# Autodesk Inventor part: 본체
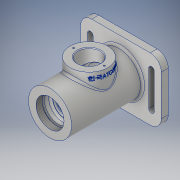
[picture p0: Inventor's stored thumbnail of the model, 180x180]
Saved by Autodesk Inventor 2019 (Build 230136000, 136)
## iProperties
Created: 2021-07
Part Number: 본체
Material: 알루미늄 6061
Document SubType Name: Modeling
Designer: jun-2-7
Mass: 744.735 g
Surface Area: 645.369 cm^2
Volume: 275.828 cm^3
Density: 2.7 g/cm^3
Appearance: 알루미늄 - 평지
Author: jun-2-7
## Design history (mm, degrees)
sketch "스케치1"
  geometry: L1 (0, 51)-(31, 51); L2 (31, 51)-(31, -51); L3 (31, -51)-(0, -51); L4 (-6.2, 0)-(37.2, 0) reference; L5 (0, -71.4)-(0, 71.4) reference; L6 (0, 51)-(0, -51); L7 (0, 51)-(0, -51); 1 further point
  constraints: 10 end point, 2 collinear, 2 perpendicular, 2 point on line, 1 horizontal, 1 other
  dimensions: "d0" = 102 distance of L1.end L2.end; "d1" = 62 diameter of L2 L5
revolve "회전1" sketch "스케치1" stored, may be unused: angle "d2" = 90 deg
sketch "스케치2"
  geometry: L1 (58, -45)-(-58, -45); L2 (-58, -45)-(-58, 45); L3 (-58, 45)-(58, 45); L4 (58, 45)-(58, -45); L5 (58, -45)-(-58, 45); L6 (-58, -45)-(58, 45); 1 further point
  constraints: 12 end point, 2 midpoint, 2 parallel, 1 horizontal, 1 perpendicular
  dimensions: "d3" = 116 distance of L2.end L3.end; "d4" = 90 distance of L3.end L1.start
extrude "돌출1" join sketch "스케치2" distance "d5" = 10; taper "d6" = 0 deg
node "작업 평면2"
sketch "스케치4"
  geometry: L1 (-31, 51)-(31, 51) reference; C1 r 27 at (0, -5); 2 further points
  constraints: 1 centre point, 1 coincident, 1 midpoint, 1 vertical alignment
  dimensions: "d8" = 54 diameter of C1; "d65" = 56 distance from line of L1 point (0, -5)
extrude "돌출2" join sketch "스케치4" stored distance "d9" = 3; taper "d10" = 0 deg
sketch "스케치5"
  geometry: C1 r 35 at (0, 0); 1 further point
  constraints: 1 centre point, 1 coincident
  dimensions: "d11" = 70 diameter of C1
extrude "돌출3" join sketch "스케치5" distance "d12" = 3; taper "d13" = 0 deg
sketch "스케치9"
  geometry: 2 further points
  constraints: 1 coincident
hole "구멍2" sketch "스케치9" at (0, 0) diameter "d21" = 40.376; stored, may be unused: countersink angle "d25" = 90 deg, drill point angle "d27" = 0 deg; dims "d22" = 9, "d23" = 4, "d24" = 2, "d26" = 9
sketch "스케치11"
  geometry: C1 r 24 at (0, 0); 1 further point
  constraints: 1 centre point, 1 coincident
  dimensions: "d32" = 48 diameter of C1
extrude "돌출4" cut sketch "스케치11" distance "d33" = 3; taper "d34" = 0 deg
sketch "스케치12"
  geometry: C1 r 20 at (0, 0); 1 further point
  constraints: 1 centre point, 1 coincident
  dimensions: "d35" = 40 diameter of C1
extrude "돌출5" cut sketch "스케치12" distance "d36" = 9; taper "d37" = 0 deg
fillet "모깎기1" dims "d39" = 3
revolve "회전2" stored, may be unused: angle "d89" = 90 deg
fillet "모깎기3" dims "d90" = 16
sketch "스케치21"
  geometry: L1 (42, -45)-(-42, -45) reference; L2 (-58, -29)-(-58, 29) reference; L3 (-42, 45)-(42, 45) reference; L4 (58, 29)-(58, -29) reference; L5 (85.839, 0)-(-85.839, 0) reference; L6 (0, -67.639)-(0, 67.639) reference; L7 (-44, 25)-(-44, -25); L8 (-40, 25)-(-40, -25); L9 (-48, -25)-(-48, 25); L10 (-42, 29)-(-42, -29); L11 (40, 25)-(40, -25); L12 (44, 25)-(44, -25); L13 (48, -25)-(48, 25); L14 (42, 29)-(42, -29); C1 r 31 at (0, 0) reference; A1 r 16 centre (42, -29) between (42, -45) and (58, -29) reference; A2 r 16 centre (-42, -29) between (-58, -29) and (-42, -45) reference; A3 r 16 centre (-42, 29) between (-42, 45) and (-58, 29) reference; A4 r 16 centre (42, 29) between (58, 29) and (42, 45) reference; A5 r 4 centre (-44, 25) between (-40, 25) and (-48, 25); A6 r 4 centre (-44, -25) between (-48, -25) and (-40, -25); A7 r 4 centre (44, 25) between (48, 25) and (40, 25); A8 r 4 centre (44, -25) between (40, -25) and (48, -25); 3 further points
  constraints: 20 end point, 9 symmetric about line, 8 point on circle, 4 centre point, 4 tangent, 2 vertical, 1 midpoint, 1 parallel, 1 point on line, 2 other
  dimensions: "d91" = 4 radius of A5; "d92" = 44 distance of point (0, 0) point (-44, 0); "d93" = 50 distance of L7.start L7.end
extrude "돌출10" cut sketch "스케치21" extent not by distance; stored distance "d94" = 0; taper "d95" = 0 deg
sketch "스케치22"
  geometry: C1 r 27 at (0, 0) reference; C2 r 16 at (0, 0); 1 further point
  constraints: 1 centre point, 1 coincident
  dimensions: "d96" = 32 diameter of C2
extrude "돌출11" cut sketch "스케치22" stored distance "d97" = 38; taper "d98" = 0 deg
sketch "스케치23"
  geometry: L1 (-81.2, -5)-(81.2, -5) reference; L2 (0, 82)-(0, -79) reference; C1 r 16 at (0, 0) reference; C2 r 27 at (0, 0) reference; A1 r 22 centre (0, 0) between (22, 0) and (-22, 0); 1 further point
  constraints: 2 point on circle, 1 centre point, 1 coincident
  dimensions: "d99" = 44 diameter of A1
hole "구멍3" sketch "스케치23" at (22, 0), (-22, 0) diameter "d100" = 2.459; stored, may be unused: countersink angle "d104" = 90 deg, drill point angle "d106" = 118 deg; dims "d101" = 6, "d102" = 4, "d103" = 2, "d105" = 8
node "작업 평면3"
sketch "스케치24"
  geometry: L1 (-105, 5)-(21, 5) reference; L2 (-42, -82)-(-42, 79) reference; L3 (0, 27)-(0, -27) reference; L4 (17.704, 0)-(-49.483, 0); L5 (0, 27)-(-11, 27) reference; 2 further points
  constraints: 2 end point, 1 horizontal, 1 other
  dimensions: "d107" = 27 distance from line of L3.end L4; "d108" = 27 distance from line of point (-8, 0) L5; "d109" = 8 distance from line of point (-8, 0) L3
feature "엠보싱1" sketch "스케치24" dims "d0" = 102, "d110" = 0.5, "d111" = 0
fillet "모깎기4" dims "d112" = 3
fillet "모깎기5" dims "d113" = 3
chamfer "모따기3" distance "d114" = 1; stored, may be unused: second distance "d115" = 2, angle "d116" = 45 deg
fillet "모깎기6" dims "d121" = 3
chamfer "모따기4" distance "d122" = 0.7; stored, may be unused: second distance "d123" = 2, angle "d124" = 30 deg
node "솔리드1"
sketch "스케치20"
  geometry: L1 (-20.188, 51)-(20.188, 51) reference; L2 (20.188, 42)-(-20.188, 42) reference; L3 (-17, 30)-(17, 30) reference; L4 (20, 33)-(-20, 33) reference; L5 (0, 74)-(0, -87) reference; L6 (-63, 0)-(63, 0) reference; L7 (0, -87)-(0, 74) reference; L8 (-17, 30)-(17, 30) reference; L9 (0, 30)-(17.5, 30); L10 (17.5, 30)-(17.5, 26.75); L11 (17.5, 26.75)-(18.5, 26.75); L12 (18.5, 26.75)-(18.5, 25); L13 (18.5, 25)-(17.5, 25); L14 (17.5, 25)-(17.5, 15); L15 (18.5, 14)-(23, 14); L16 (26, 11)-(26, -21); L17 (-31, 51)-(31, 51) reference; L18 (23, -24)-(18.5, -24); L19 (17.5, -25)-(17.5, -34.7); L20 (17.2, -35)-(16, -35); L21 (16, -35)-(16, -37); L22 (13, -40)-(10, -40); L23 (10, -40)-(10, -46.693); L24 (10, -46.693)-(12.2, -46.693); L25 (12.5, -46.993)-(12.5, -49.3); L26 (16, -53.993)-(22, -64); L27 (-35, -64)-(35, -64) reference; L28 (17.5, 15)-(18.5, 14); L29 (18.5, -24)-(17.5, -25); L30 (0, 30)-(0, -64); L31 (0, -64)-(22, -64); L32 (16, -53.993)-(12.5, -53.993); L33 (12.5, -53.993)-(12.5, -49.3); A1 r 0.3 centre (12.2, -46.993) between (12.5, -46.993) and (12.2, -46.693); A2 r 3 centre (23, 11) between (26, 11) and (23, 14); A3 r 3 centre (23, -21) between (23, -24) and (26, -21); A4 r 0.3 centre (17.2, -34.7) between (17.2, -35) and (17.5, -34.7); A5 r 3 centre (13, -37) between (13, -40) and (16, -37); 7 further points
  constraints: 46 end point, 14 point on line, 13 perpendicular, 10 point on circle, 10 tangent, 5 centre point, 3 midpoint, 2 horizontal, 1 collinear, 1 equal radius, 1 vertical
  dimensions: "d59" = 35 diameter of L10 L5; "d60" = 1.75 distance of L11.end L12.end; "d61" = 37 diameter of L12 L5; "d62" = 11 distance of L13.end point (17.5, 14); "d64" = 56 distance from line of point (26, -5) L17; "d66" = 38 distance of point (26, 14) point (26, -24); "d67" = 52 diameter of L16 L5; "d68" = 35 diameter of L19 L5; "d69" = 32 diameter of L21 L5; "d70" = 20 diameter of L23 L5; "d71" = 25 diameter of L25 L5; "d72" = 44 diameter of L26.end L5; "d73" = 11 distance of point (17.5, -24) point (17.5, -35); "d75" = 24 distance from line of L27 L22.end; "d78" = 0.3 radius of A1; "d82" = 1 distance of L14.end point (17.5, 14); "d83" = 1 distance of L15.start point (17.5, 14) (= d82); "d84" = 3 radius of A2 (derived); "d85" = 1 distance of L18.end point (17.5, -24); "d86" = 1 distance of L19.start point (17.5, -24) (= d85); "d87" = 0.3 radius of A4; "d88" = 3 radius of A5; "d118" = 10.00731 vertical distance of L32.end L26.end; "d119" = 16 distance from line of L30 L26.start; "d120" = 7.3 distance between parallel lines of L32 L24
node "투영된 루프5"
node "투영된 루프6"
node "투영된 루프7"
node "투영된 루프8"
node "투영된 루프9"
other parameters: "d7" = 42
